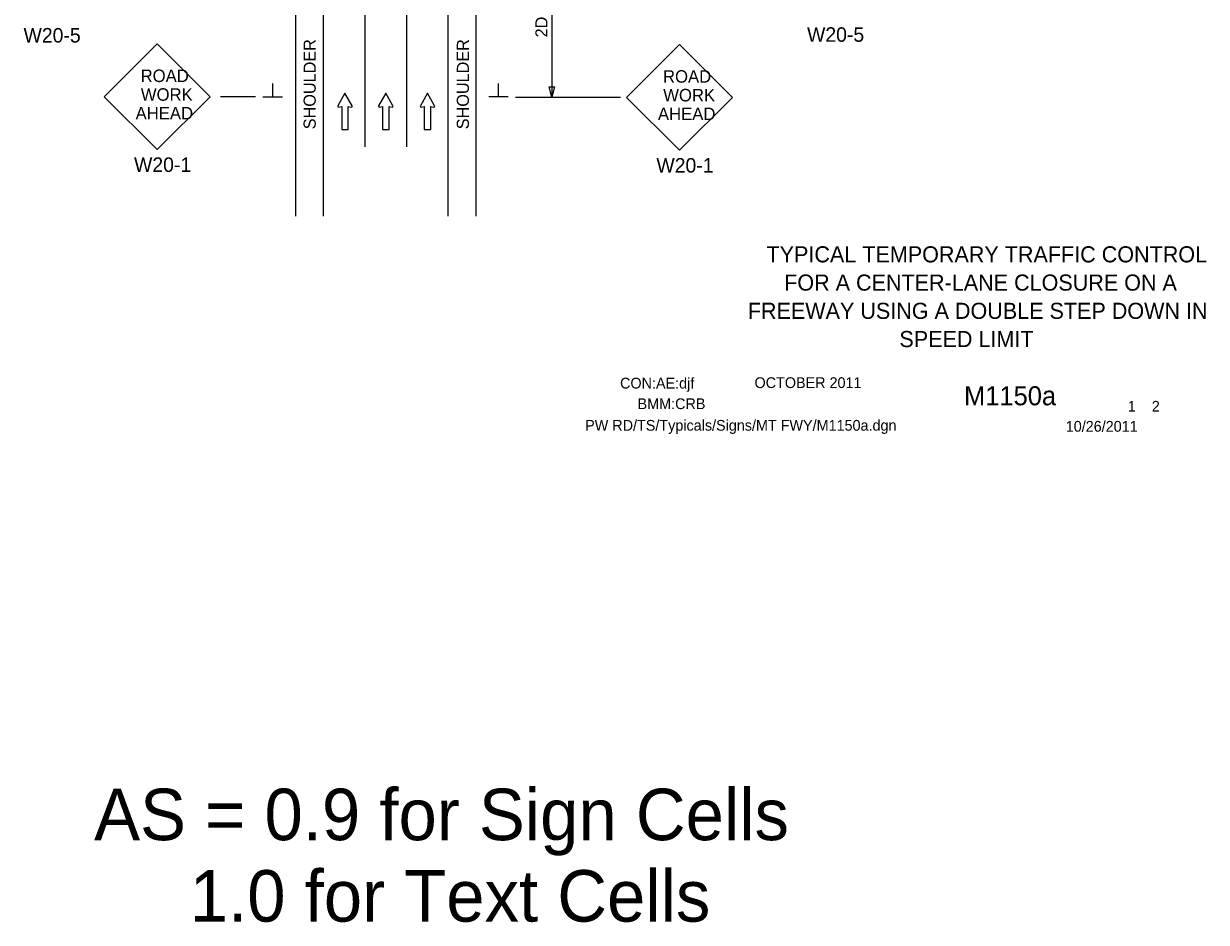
# Model space of a CAD drawing. Extents: x 16726 to 18482, y 5650 to 7013.
# Drawn here: x 16746 to 17429, y 5650 to 6169 of the extents above; entities that cross this region are included whole.
import ezdxf

# ---------------------------------------------------------------- set-up
doc = ezdxf.new("R2010")
doc.units = 0
for name, color, linetype in [('ALI_LEGAL_EX', 7, 'Continuous'), ('BORDER', 7, 'Continuous'), ('BORDER_SIGNAL_WO', 7, 'Continuous'), ('MT_SCRATCH_LEVEL_E', 7, 'Continuous'), ('PAVT_EDGE_EX', 7, 'Continuous'), ('TRAFFIC_SIGNS_PR', 7, 'Continuous'), ('TYPICAL_TEXT_DIMEN_PR', 7, 'Continuous')]:
    doc.layers.add(name, color=color, linetype=linetype)

msp = doc.modelspace()

# ---------------------------------------------------------------- linework, layer by layer
at = {"layer": 'ALI_LEGAL_EX'}
for p, q in [((16943.36, 6961.56), (16943.36, 6097.65)), ((16967.36, 6961.56), (16967.36, 6097.65))]:
    msp.add_line(p, q, dxfattribs=at)
for points in [[(16943.36, 6124.34), (16943.36, 6105.42)], [(16943.36, 6124.34), (16943.36, 6099.34)], [(16967.36, 6124.34), (16967.36, 6105.42)], [(16967.36, 6124.34), (16967.36, 6099.34)]]:
    msp.add_lwpolyline(points, dxfattribs=at)
at = {"layer": 'MT_SCRATCH_LEVEL_E'}
for p, q in [((16931.92, 6128.45), (16927.81, 6121.22)), ((16936.06, 6121.22), (16931.92, 6128.45)), ((16955.46, 6128.45), (16951.35, 6121.22)), ((16959.61, 6121.22), (16955.46, 6128.45)), ((16979.53, 6128.45), (16975.42, 6121.22)), ((16983.68, 6121.22), (16979.53, 6128.45)), ((16928.29, 6120.53), (16930.06, 6120.85)), ((16930.06, 6120.85), (16930.06, 6107.59)), ((16933.81, 6107.59), (16933.81, 6120.85)), ((16933.81, 6120.85), (16935.58, 6120.53)), ((16951.83, 6120.53), (16953.61, 6120.85)), ((16953.61, 6120.85), (16953.61, 6107.59)), ((16957.35, 6107.59), (16957.35, 6120.85)), ((16957.35, 6120.85), (16959.13, 6120.53)), ((16975.91, 6120.53), (16977.68, 6120.85)), ((16977.68, 6120.85), (16977.68, 6107.59)), ((16981.42, 6107.59), (16981.42, 6120.85)), ((16981.42, 6120.85), (16983.2, 6120.53)), ((16930.06, 6107.59), (16933.81, 6107.59)), ((16953.61, 6107.59), (16957.35, 6107.59)), ((16977.68, 6107.59), (16981.42, 6107.59))]:
    msp.add_line(p, q, dxfattribs=at)
for centre, start, end in [((16928.21, 6120.99), 150.42484, 279.96381), ((16935.65, 6120.99), 260.03619, 29.77312), ((16951.76, 6120.99), 150.42484, 279.96381), ((16959.2, 6120.99), 260.03619, 29.77312), ((16975.83, 6120.99), 150.42484, 279.96381), ((16983.27, 6120.99), 260.03619, 29.77312)]:
    msp.add_arc(centre, 0.463, start, end, dxfattribs=at)
at = {"layer": 'PAVT_EDGE_EX'}
for p, q in [((16903.36, 6926.44), (16903.36, 6057.56)), ((16919.36, 6926.44), (16919.36, 6057.56)), ((16991.36, 6926.44), (16991.36, 6057.56)), ((17007.36, 6926.44), (17007.36, 6057.56))]:
    msp.add_line(p, q, dxfattribs=at)
at = {"layer": 'TRAFFIC_SIGNS_PR'}
for p, q in [((16823.5, 6157.03), (16792.95, 6126.48)), ((16854.05, 6126.48), (16823.5, 6157.03)), ((17124.98, 6156.67), (17094.43, 6126.12)), ((17155.53, 6126.12), (17124.98, 6156.67)), ((16792.95, 6126.48), (16823.5, 6095.94)), ((16823.5, 6095.94), (16854.05, 6126.48)), ((17094.43, 6126.12), (17124.98, 6095.57)), ((17124.98, 6095.57), (17155.53, 6126.12))]:
    msp.add_line(p, q, dxfattribs=at)
at = {"layer": 'TYPICAL_TEXT_DIMEN_PR'}
for p, q in [((17051.36, 6201.26), (17051.36, 6126.26)), ((16890.23, 6126.41), (16890.23, 6134.2)), ((17020.48, 6126.41), (17020.48, 6134.2)), ((17051.36, 6126.26), (17049.79, 6132.12)), ((17049.79, 6132.12), (17051.36, 6132.12)), ((17051.36, 6132.12), (17052.93, 6132.12)), ((17052.93, 6132.12), (17051.36, 6126.26)), ((16880.36, 6126.41), (16860.16, 6126.41)), ((16884.61, 6126.41), (16895.86, 6126.41)), ((17026.11, 6126.41), (17014.86, 6126.41)), ((17030.36, 6126.26), (17090.92, 6126.26))]:
    msp.add_line(p, q, dxfattribs=at)

# ---------------------------------------------------------------- texts
at = {"layer": 'BORDER'}
for s, p in [('TYPICAL TEMPORARY TRAFFIC CONTROL', (17175.21, 6030.86)), ('FOR A CENTER-LANE CLOSURE ON A', (17185.42, 6014.56)), ('FREEWAY USING A DOUBLE STEP DOWN IN ', (17164.42, 5998.26)), ('SPEED LIMIT', (17251.92, 5981.96))]:
    msp.add_text(s, height=9.3, dxfattribs=at).set_placement(p)
at = {"layer": 'BORDER_SIGNAL_WO'}
for s, height, p in [('CON:AE:djf  ', 6.2, (17090.69, 5958.06)), ('    OCTOBER 2011    ', 6.2, (17159.08, 5958.34)), ('    M1150a   ', 11, (17272.86, 5948.38)), ('BMM:CRB   ', 6.2, (17100.81, 5946.17)), (' 1    2 ', 6.2, (17381.45, 5944.7)), ('PW RD/TS/Typicals/Signs/MT FWY/M1150a.dgn      ', 6.2, (17070.55, 5933.71)), ('10/26/2011    ', 6.2, (17347.93, 5933.13)), ('AS = 0.9 for Sign Cells', 29.7271, (16787.14, 5697.35)), ('     1.0 for Text Cells', 29.7271, (16787.14, 5650.34))]:
    msp.add_text(s, height=height, dxfattribs=at).set_placement(p)
at = {"layer": 'TRAFFIC_SIGNS_PR'}
for s, height, p in [('W20-5', 8.37, (16746.42, 6157.77)), ('W20-5', 8.37, (17198.62, 6158.19)), ('ROAD', 7.2, (16813.98, 6134.96)), ('ROAD', 7.2, (17115.47, 6134.6)), ('WORK', 7.2, (16814.11, 6124.16)), ('WORK', 7.2, (17115.59, 6123.8)), ('AHEAD', 7.2, (16811.08, 6113.36)), ('AHEAD', 7.2, (17112.56, 6113)), ('W20-1', 8.37, (16810.19, 6083.07)), ('W20-1', 8.37, (17111.67, 6082.7))]:
    msp.add_text(s, height=height, dxfattribs=at).set_placement(p)
at = {"layer": 'TYPICAL_TEXT_DIMEN_PR'}
for s, p in [('2D', (17048.8, 6160.73)), ('SHOULDER', (16915.04, 6107.71)), ('SHOULDER', (17003.47, 6107.71))]:
    msp.add_text(s, height=7, rotation=90, dxfattribs=at).set_placement(p)

doc.saveas('drawing.dxf')
